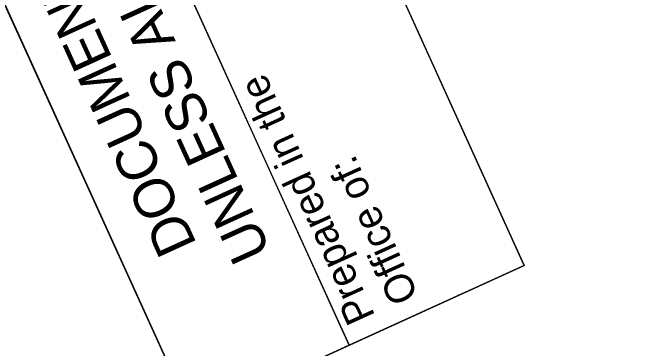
# Model space of a CAD drawing. Extents: x 2096093 to 2099001, y 683546 to 685907.
# Drawn here: x 2097556.6 to 2097638.8, y 685362.9 to 685405.5 of the extents above; entities that cross this region are included whole.
import ezdxf

# ---------------------------------------------------------------- set-up
doc = ezdxf.new("R2010")
doc.units = 0
for name, color, linetype in [('Old_Level_2', 7, 'Continuous'), ('Scratch_Level_4', 7, 'Continuous'), ('Sheet Block Title CELL', 7, 'Continuous'), ('Sheet Layout Plan Border', 7, 'Continuous'), ('Sheet Sticker Exception Certification CELL', 7, 'Continuous')]:
    doc.layers.add(name, color=color, linetype=linetype)

msp = doc.modelspace()

# ---------------------------------------------------------------- linework, layer by layer
at = {"layer": 'Old_Level_2'}
msp.add_lwpolyline([(2097478.084, 685308.034), (2097400.684, 685478.205), (2097502.067, 685524.318), (2097579.467, 685354.147)], close=True, dxfattribs=at)
msp.add_lwpolyline([(2097478.084, 685308.034), (2097400.684, 685478.205), (2097502.067, 685524.318), (2097579.467, 685354.147)], close=True, dxfattribs=at)
at = {"layer": 'Scratch_Level_4'}
msp.add_lwpolyline([(2097576.737, 685472.345), (2098256.773, 685779.318), (2098363.728, 685544.169), (2098430.064, 685574.342), (2098911.143, 684517.116), (2097955.365, 684082.388), (2097417.224, 685265.53), (2097411.626, 685277.836), (2097412.446, 685278.179), (2097621.751, 685373.38)], close=True, dxfattribs=at)
at = {"layer": 'Sheet Block Title CELL'}
msp.add_lwpolyline([(2097599.439, 685363.231), (2097522.114, 685533.236), (2097544.426, 685543.384), (2097621.751, 685373.38)], close=True, dxfattribs=at)
at = {"layer": 'Sheet Layout Plan Border'}
msp.add_lwpolyline([(2097576.737, 685472.345), (2098256.773, 685779.318), (2098363.728, 685544.169), (2098430.064, 685574.342), (2098911.143, 684517.116), (2097955.365, 684082.388), (2097417.224, 685265.53), (2097411.626, 685277.836), (2097412.446, 685278.179), (2097621.751, 685373.38)], close=True, dxfattribs=at)
at = {"layer": 'Sheet Sticker Exception Certification CELL'}
for p, q in [((2097522.114, 685533.236), (2097599.439, 685363.231)), ((2097522.114, 685533.236), (2097599.439, 685363.231)), ((2097579.467, 685354.147), (2097502.142, 685524.152)), ((2097579.467, 685354.147), (2097502.142, 685524.152)), ((2097599.439, 685363.231), (2097579.467, 685354.147)), ((2097599.439, 685363.231), (2097579.467, 685354.147))]:
    msp.add_line(p, q, dxfattribs=at)

# ---------------------------------------------------------------- texts
at = {"layer": 'Sheet Block Title CELL'}
for s, height, p in [('Prepared in the ', 3.73527, (2097602.811, 685366.942)), ('Office of:', 3.7353, (2097608.336, 685369.455))]:
    msp.add_text(s, height=height, rotation=114.45798, dxfattribs=at).set_placement(p)
at = {"layer": 'Sheet Sticker Exception Certification CELL'}
for s, p in [('UNLESS ALL SIGNATURES COMPLETED', (2097589.553, 685375.146)), ('UNLESS ALL SIGNATURES COMPLETED', (2097589.553, 685375.146)), ('DOCUMENT NOT CONSIDERED FINAL', (2097580.114, 685376.054)), ('DOCUMENT NOT CONSIDERED FINAL', (2097580.114, 685376.054))]:
    msp.add_text(s, height=5.13504, rotation=114.45798, dxfattribs=at).set_placement(p)

doc.saveas('drawing.dxf')
